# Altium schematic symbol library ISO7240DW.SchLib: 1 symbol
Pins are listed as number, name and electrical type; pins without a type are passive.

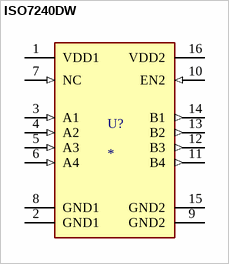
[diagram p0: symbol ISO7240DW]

## ISO7240DW
designator U?
MP: ISO7241CDWR
footprint ISO7240DW
pins: 1 VDD1 (power), 2 GND1 (power), 3 A1 (in), 4 A2 (in), 5 A3 (in), 6 A4 (in), 7 NC (in), 8 GND1 (power), 9 GND2 (power), 10 EN2 (in), 11 B4 (out), 12 B3 (out), 13 B2 (out), 14 B1 (out), 15 GND2 (power), 16 VDD2 (power)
